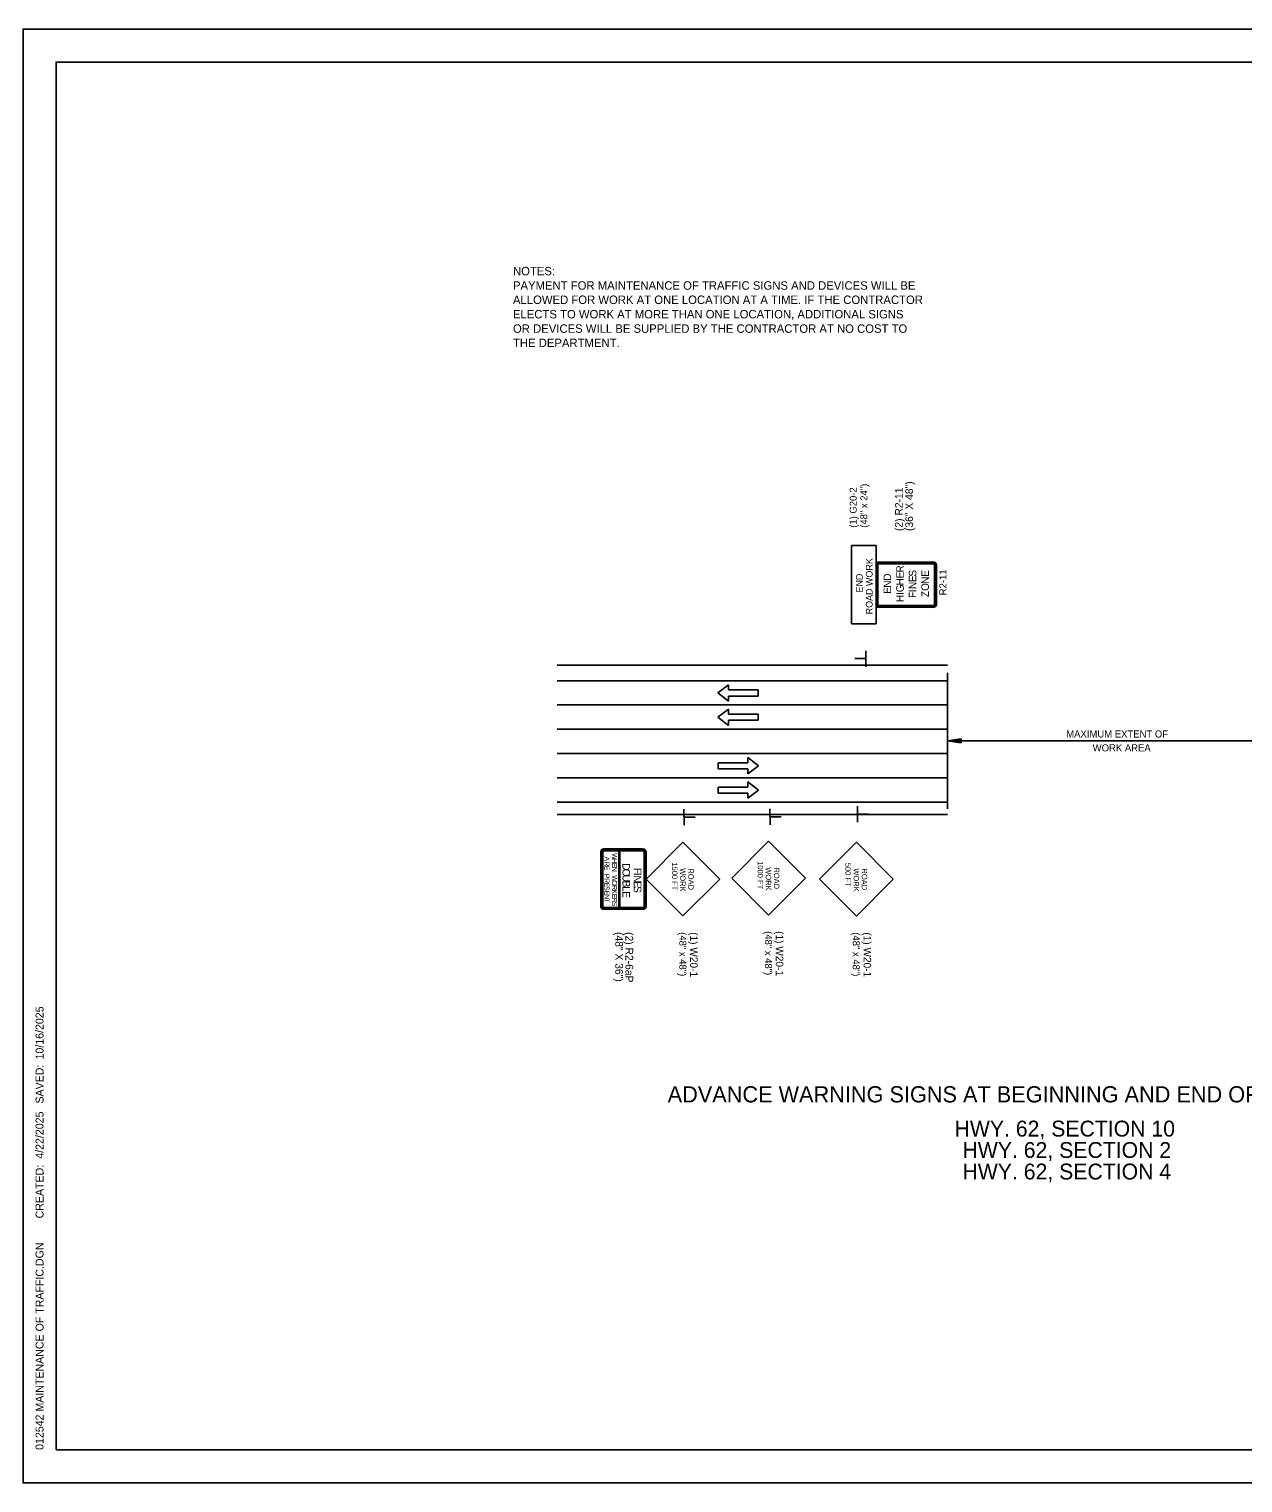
# Model space of a CAD drawing. Extents: x 32485 to 39285, y 55121 to 58033.
# Drawn here: x 34190 to 35108, y 56764 to 57864 of the extents above; entities that cross this region are included whole.
import ezdxf

# ---------------------------------------------------------------- set-up
doc = ezdxf.new("R2010")
doc.units = 0
for name, color, linetype in [('Default', 7, 'Continuous'), ('R_Border', 7, 'Continuous'), ('R_Border Notes', 7, 'Continuous'), ('R_Draft', 7, 'Continuous'), ('R_Exist Surface', 7, 'Continuous'), ('SHET_Annotations', 7, 'Continuous')]:
    doc.layers.add(name, color=color, linetype=linetype)

msp = doc.modelspace()

# ---------------------------------------------------------------- linework, layer by layer
at = {"layer": 'Default'}
for p, q in [((34830.2, 57458.5), (34830.2, 57428.5)), ((34830.8, 57458.5), (34830.8, 57428.5)), ((34831.7, 57428.5), (34831.7, 57458.5)), ((34873.8, 57460.6), (34832.4, 57460.6)), ((34873.8, 57460.1), (34832.4, 57460.1)), ((34832.4, 57459.2), (34873.8, 57459.2)), ((34874.5, 57458.5), (34874.5, 57428.5)), ((34875.3, 57428.5), (34875.3, 57458.5)), ((34875.9, 57428.5), (34875.9, 57458.5)), ((34873.8, 57427.8), (34832.4, 57427.8)), ((34832.4, 57427), (34873.8, 57427)), ((34832.4, 57426.4), (34873.8, 57426.4)), ((34884.4, 57376.8), (34884.4, 57273.9)), ((34710.5, 57361.6), (34718.5, 57367.7)), ((34718.5, 57363.9), (34718.5, 57367.7)), ((34718.5, 57355.5), (34710.5, 57361.6)), ((34718.5, 57363.9), (34741.1, 57363.9)), ((34718.5, 57359.3), (34741.1, 57359.3)), ((34718.5, 57355.5), (34718.5, 57359.3)), ((34741.1, 57359.3), (34741.1, 57363.9)), ((34710.5, 57343.2), (34718.5, 57349.3)), ((34718.5, 57337.1), (34710.5, 57343.2)), ((34718.5, 57345.5), (34718.5, 57349.3)), ((34718.5, 57345.5), (34741.1, 57345.5)), ((34741.1, 57340.9), (34741.1, 57345.5)), ((34718.5, 57340.9), (34741.1, 57340.9)), ((34718.5, 57337.1), (34718.5, 57340.9)), ((34884.4, 57325.4), (35148.1, 57325.4)), ((34941.7, 57325.4), (35090.8, 57325.4)), ((34733.3, 57312.7), (34733.3, 57308.8)), ((34733.3, 57312.7), (34741.2, 57306.5)), ((34733.3, 57308.8), (34710.7, 57308.8)), ((34710.7, 57308.8), (34710.7, 57304.2)), ((34733.3, 57304.2), (34710.7, 57304.2)), ((34741.2, 57306.5), (34733.3, 57300.4)), ((34733.3, 57304.2), (34733.3, 57300.4)), ((34733.3, 57290.4), (34710.7, 57290.4)), ((34710.7, 57290.4), (34710.7, 57285.8)), ((34733.3, 57294.3), (34733.3, 57290.4)), ((34733.3, 57294.3), (34741.2, 57288.1)), ((34741.2, 57288.1), (34733.3, 57282)), ((34733.3, 57285.8), (34710.7, 57285.8)), ((34733.3, 57285.8), (34733.3, 57282)), ((34622.1, 57241.5), (34622.1, 57200.1)), ((34622.7, 57241.5), (34622.7, 57200.1)), ((34623.5, 57200.1), (34623.5, 57241.5)), ((34654.2, 57243.7), (34624.2, 57243.7)), ((34654.2, 57243.1), (34624.2, 57243.1)), ((34624.2, 57242.2), (34654.2, 57242.2)), ((34635.7, 57199.4), (34635.7, 57242.2)), ((34635.7, 57242.2), (34636.5, 57242.2)), ((34636.5, 57242.2), (34636.5, 57199.4)), ((34654.9, 57241.5), (34654.9, 57200.1)), ((34655.7, 57200.1), (34655.7, 57241.5)), ((34656.3, 57200.1), (34656.3, 57241.5)), ((34654.2, 57199.4), (34624.2, 57199.4)), ((34624.2, 57198.6), (34654.2, 57198.6)), ((34624.2, 57198), (34654.2, 57198)), ((34636.5, 57199.4), (34635.7, 57199.4))]:
    msp.add_line(p, q, dxfattribs=at)
msp.add_lwpolyline([(34185, 57863.9), (34185, 56763.9), (35885, 56763.9), (35885, 57863.9)], close=True, dxfattribs=at)
for centre, radius, start, end in [((34832.4, 57458.5), 2.14, 90, 180), ((34832.4, 57458.5), 1.55, 90, 180), ((34832.4, 57458.5), 0.714, 90, 180), ((34873.8, 57458.5), 2.14, 0, 90), ((34873.8, 57458.5), 1.55, 0, 90), ((34873.8, 57458.5), 0.714, 0, 90), ((34832.4, 57428.5), 2.14, 180, 270), ((34832.4, 57428.5), 1.55, 180, 270), ((34832.4, 57428.5), 0.714, 180, 270), ((34873.8, 57428.5), 2.14, 270, 0), ((34873.8, 57428.5), 1.55, 270, 0), ((34873.8, 57428.5), 0.714, 270, 0), ((34624.2, 57241.5), 2.14, 90, 180), ((34624.2, 57241.5), 1.55, 90, 180), ((34624.2, 57241.5), 0.714, 90, 180), ((34654.2, 57241.5), 2.14, 0, 90), ((34654.2, 57241.5), 1.55, 0, 90), ((34654.2, 57241.5), 0.714, 0, 90), ((34624.2, 57200.1), 2.14, 180, 270), ((34624.2, 57200.1), 1.55, 180, 270), ((34624.2, 57200.1), 0.714, 180, 270), ((34654.2, 57200.1), 2.14, 270, 0), ((34654.2, 57200.1), 1.55, 270, 0), ((34654.2, 57200.1), 0.714, 270, 0)]:
    msp.add_arc(centre, radius, start, end, dxfattribs=at)
at = {"layer": 'R_Border'}
for p, q in [((34811.6, 57473.1), (34811.6, 57413.9)), ((34830.2, 57473.1), (34811.6, 57473.1)), ((34830.2, 57473.1), (34830.2, 57413.9)), ((34830.2, 57413.9), (34811.6, 57413.9)), ((34822.4, 57387.6), (34814.2, 57387.6)), ((34822.6, 57393.6), (34822.6, 57381.5)), ((34685.1, 57261.6), (34684.9, 57273.6)), ((34685.1, 57267.6), (34693.4, 57267.7)), ((34750.2, 57261.9), (34750, 57273.9)), ((34750.2, 57267.9), (34758.5, 57268)), ((34816.3, 57263.8), (34816.1, 57275.9)), ((34816.4, 57269.8), (34824.6, 57269.9)), ((34656.3, 57220.8), (34684.2, 57248.7)), ((34712.1, 57220.8), (34684.2, 57248.7)), ((34721.1, 57221.5), (34749, 57249.4)), ((34776.9, 57221.5), (34749, 57249.4)), ((34787.5, 57220.7), (34815.4, 57248.6)), ((34843.3, 57220.7), (34815.4, 57248.6)), ((34684.2, 57192.9), (34656.3, 57220.8)), ((34684.2, 57192.9), (34712.1, 57220.8)), ((34749, 57193.6), (34721.1, 57221.5)), ((34749, 57193.6), (34776.9, 57221.5)), ((34815.4, 57192.8), (34787.5, 57220.7)), ((34815.4, 57192.8), (34843.3, 57220.7))]:
    msp.add_line(p, q, dxfattribs=at)
at = {"layer": 'R_Border Notes'}
msp.add_line((34326.1, 57842.5), (34326.1, 57842.5), dxfattribs=at)
msp.add_line((34326.1, 57842.5), (34326.1, 57842.5), dxfattribs=at)
for points in [[(34185, 56763.9), (35885, 56763.9), (35885, 57863.9), (34185, 57863.9)], [(34210, 56788.9), (35860, 56788.9), (35860, 57838.9), (34210, 57838.9)]]:
    msp.add_lwpolyline(points, close=True, dxfattribs=at)
at = {"layer": 'R_Draft'}
for p, q in [((34894.7, 57326.9), (34884.4, 57325.4)), ((34894.7, 57323.8), (34884.4, 57325.4)), ((34894.7, 57326.7), (34886.1, 57325.4)), ((34894.7, 57324.1), (34886.1, 57325.4)), ((34894.7, 57326.4), (34887.9, 57325.4)), ((34894.7, 57324.4), (34887.9, 57325.4)), ((34894.7, 57326.1), (34889.6, 57325.4)), ((34894.7, 57324.6), (34889.6, 57325.4)), ((34894.7, 57325.9), (34891.3, 57325.4)), ((34894.7, 57324.9), (34891.3, 57325.4)), ((34894.7, 57325.6), (34893.1, 57325.4)), ((34894.7, 57325.1), (34893.1, 57325.4)), ((34894.7, 57323.8), (34894.7, 57326.9))]:
    msp.add_line(p, q, dxfattribs=at)
at = {"layer": 'R_Exist Surface'}
for p, q in [((34589.1, 57382.7), (34884.4, 57382.7)), ((34589.1, 57370.9), (34884.4, 57370.9)), ((34589.1, 57352.5), (34884.4, 57352.5)), ((34589.1, 57334.1), (34884.4, 57334.1)), ((34589.1, 57315.7), (34884.4, 57315.7)), ((34589.1, 57297.3), (34884.4, 57297.3)), ((34589.1, 57278.9), (34884.4, 57278.9)), ((34589.1, 57269.7), (34884.4, 57269.7))]:
    msp.add_line(p, q, dxfattribs=at)

# ---------------------------------------------------------------- texts
at = {"layer": 'Default'}
for s, height, p in [('NOTES: ', 6.39, (34555.6, 57677.6)), ('PAYMENT FOR MAINTENANCE OF TRAFFIC SIGNS AND DEVICES WILL BE ', 6.392, (34555.6, 57666.7)), ('ALLOWED FOR WORK AT ONE LOCATION AT A TIME. IF THE CONTRACTOR', 6.392, (34555.6, 57655.9)), ('ELECTS TO WORK AT MORE THAN ONE LOCATION, ADDITIONAL SIGNS', 6.392, (34555.6, 57645)), ('OR DEVICES WILL BE SUPPLIED BY THE CONTRACTOR AT NO COST TO ', 6.392, (34555.6, 57634.1)), ('THE DEPARTMENT.', 6.392, (34555.6, 57623.3)), ('MAXIMUM EXTENT OF ', 5.37, (34974.1, 57327.9)), ('WORK AREA', 5.37, (34994.1, 57317.4)), ('ADVANCE WARNING SIGNS AT BEGINNING AND END OF WORK ZONE ', 12.273, (34672.6, 57051.8)), ('HWY. 62, SECTION 10', 12, (34889.6, 57026)), ('HWY. 62, SECTION 2', 12, (34895.6, 57009.8)), ('HWY. 62, SECTION 4', 12, (34895.6, 56993.5))]:
    msp.add_text(s, height=height, dxfattribs=at).set_placement(p)
for s, height, rotation, p in [('R', 5.71, 90, (34851.2, 57452.7)), ('S', 5.71, 90, (34860.7, 57449.6)), ('E', 5.71, 90, (34870.2, 57449.4)), ('R2-11', 5.38, 90, (34883.5, 57435.5)), ('D', 5.71, 90, (34841.6, 57446.5)), ('N', 5.71, 90, (34841.6, 57441.2)), ('G', 5.71, 90, (34851.2, 57437.8)), ('E', 5.71, 90, (34851.2, 57448.2)), ('H', 5.71, 90, (34851.2, 57443)), ('E', 5.71, 90, (34860.7, 57445.5)), ('N', 5.71, 90, (34860.7, 57440.2)), ('O', 5.71, 90, (34870.2, 57438.8)), ('N', 5.71, 90, (34870.2, 57444.1)), ('E', 5.71, 90, (34841.6, 57436.7)), ('I', 5.71, 90, (34851.2, 57435.7)), ('H', 5.71, 90, (34851.2, 57430.4)), ('I', 5.71, 90, (34860.7, 57437.9)), ('F', 5.71, 90, (34860.7, 57433.5)), ('Z', 5.71, 90, (34870.2, 57434.1)), ('A', 3.81, 270, (34624.8, 57237.9)), ('R', 3.81, 270, (34624.8, 57234.1)), ('W', 3.81, 270, (34630.5, 57240.5)), ('H', 3.81, 270, (34630.5, 57236.6)), ('E', 3.81, 270, (34624.8, 57230.8)), ('P', 3.81, 270, (34624.8, 57224.7)), ('E', 3.81, 270, (34630.5, 57233.1)), ('N', 3.81, 270, (34630.5, 57230)), ('W', 3.81, 270, (34630.5, 57223.7)), ('D', 5.71, 270, (34638.4, 57232.8)), ('O', 5.71, 270, (34638.4, 57228.6)), ('U', 5.71, 270, (34638.4, 57224.1)), ('F', 5.71, 270, (34647, 57229.3)), ('I', 5.71, 270, (34647, 57225.6)), ('N', 5.71, 270, (34647, 57223.6)), ('S', 3.81, 270, (34624.8, 57215.5)), ('R', 3.81, 270, (34624.8, 57221.5)), ('E', 3.81, 270, (34624.8, 57218.3)), ('E', 3.81, 270, (34624.8, 57212.3)), ('O', 3.81, 270, (34630.5, 57219.8)), ('R', 3.81, 270, (34630.5, 57216.2)), ('K', 3.81, 270, (34630.5, 57213)), ('B', 5.71, 270, (34638.4, 57219.6)), ('L', 5.71, 270, (34638.4, 57215.4)), ('E', 5.71, 270, (34638.4, 57211.7)), ('S', 5.71, 270, (34647, 57215.5)), ('E', 5.71, 270, (34647, 57219.1)), ('N', 3.81, 270, (34624.8, 57209.3)), ('T', 3.81, 270, (34624.8, 57206.1)), ('S', 3.81, 270, (34630.5, 57203.7)), ('E', 3.81, 270, (34630.5, 57209.7)), ('R', 3.81, 270, (34630.5, 57206.7))]:
    msp.add_text(s, height=height, rotation=rotation, dxfattribs=at).set_placement(p)
at = {"layer": 'R_Border'}
for s, height, rotation, p in [('(48" x 24")', 5.352, 90, (34823.7, 57486.6)), ('(1) G20-2', 5.35, 90, (34815.6, 57486.6)), ('ROAD WORK', 5.06, 90, (34827.6, 57421.1)), ('END', 5.06, 90, (34820.1, 57437.6)), ('1000 FT', 4.11, 270.0006, (34740.7, 57234.3)), ('1500 FT', 4.11, 270.0006, (34675.9, 57233.4)), ('WORK', 4.11, 270, (34682, 57229)), ('ROAD', 4.11, 270.0004, (34688.2, 57228.9)), ('WORK', 4.11, 270, (34746.8, 57229.7)), ('ROAD', 4.11, 270.0004, (34753, 57229.6)), (' 500 FT', 4.11, 270.0006, (34807, 57234.7)), ('WORK', 4.11, 270, (34813.2, 57228.9)), ('ROAD', 4.11, 270.0004, (34819.4, 57228.8)), ('(48" x 48")', 5.352, 270, (34681.4, 57180.6)), ('(1) W20-1', 5.71, 270, (34689.6, 57180.6)), ('(48" x 48")', 5.352, 270, (34746.2, 57181.4)), ('(1) W20-1', 5.71, 270, (34754.4, 57181.4)), ('(48" x 48")', 5.352, 270, (34812.6, 57180.5)), ('(1) W20-1', 5.71, 270, (34820.8, 57180.5))]:
    msp.add_text(s, height=height, rotation=rotation, dxfattribs=at).set_placement(p)
at = {"layer": 'R_Draft'}
for s, rotation, p in [('(36" X 48")', 90, (34858.2, 57484.1)), ('(2) R2-11', 90, (34850.4, 57484.1)), ('(48" X 36")', 270, (34633, 57180.7)), ('(2) R2-6aP', 270, (34640.7, 57180.7))]:
    msp.add_text(s, height=5.83, rotation=rotation, dxfattribs=at).set_placement(p)
at = {"layer": 'SHET_Annotations'}
for s, p in [('10/16/2025', (34200.5, 57084.3)), ('  SAVED: ', (34200.5, 57046.5)), ('4/22/2025', (34200.5, 57009.2)), ('     CREATED: ', (34200.5, 56952.9)), ('012542 MAINTENANCE OF TRAFFIC.DGN', (34200.5, 56788.9))]:
    msp.add_text(s, height=6, rotation=90, dxfattribs=at).set_placement(p)

doc.saveas('drawing.dxf')
